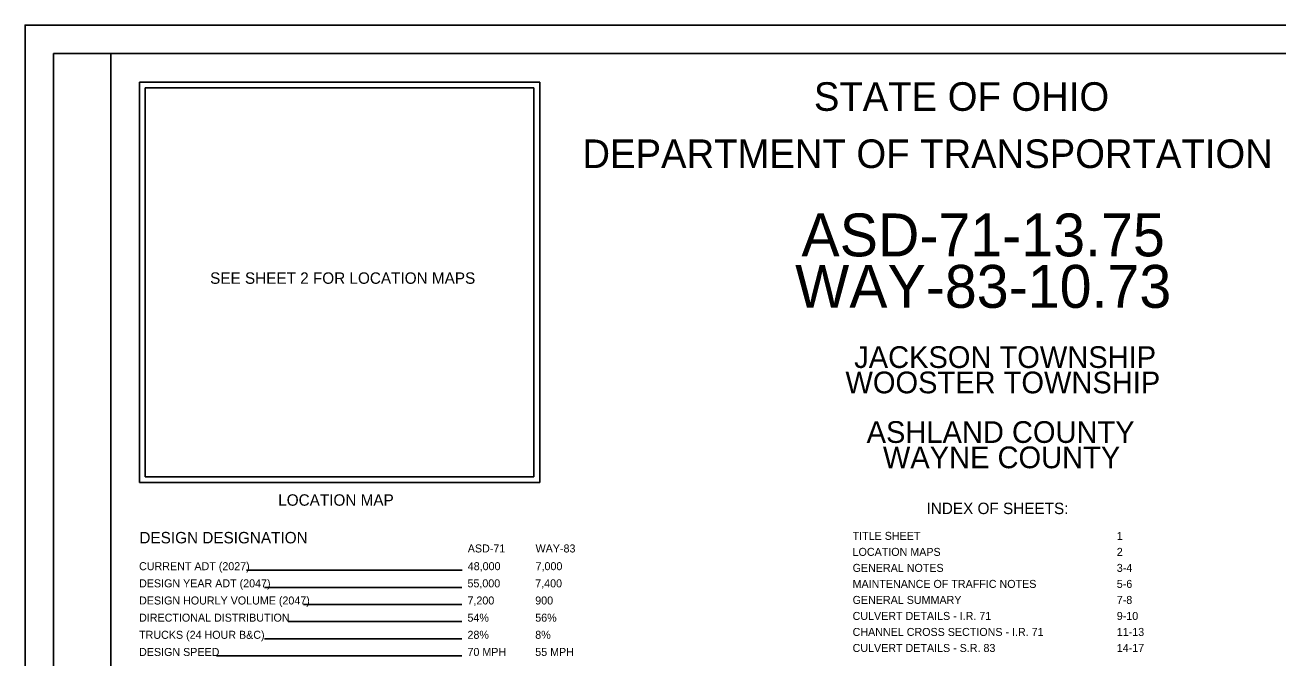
# Model space of a CAD drawing. Extents: x 0 to 34, y 0 to 22.
# Drawn here: x 0 to 21.91, y 10.93 to 22 of the extents above; entities that cross this region are included whole.
import ezdxf

# ---------------------------------------------------------------- set-up
doc = ezdxf.new("R2010")
doc.units = 0
for name, color, linetype in [('SH_Border', 7, 'Continuous'), ('SH_Cut_Line', 7, 'Continuous'), ('SH_Data', 7, 'Continuous'), ('SH_Text', 7, 'Continuous')]:
    doc.layers.add(name, color=color, linetype=linetype)

msp = doc.modelspace()

# ---------------------------------------------------------------- linework, layer by layer
at = {"layer": 'SH_Border'}
for points in [[(0.5, 21.5), (1.5, 21.5), (1.5, 0.5), (0.5, 0.5)], [(1.5, 21.5), (33.5, 21.5), (33.5, 0.5), (1.5, 0.5)]]:
    msp.add_lwpolyline(points, close=True, dxfattribs=at)
at = {"layer": 'SH_Cut_Line'}
msp.add_lwpolyline([(0, 0), (34, 0), (34, 22), (0, 22)], close=True, dxfattribs=at)
at = {"layer": 'SH_Data'}
for p, q in [((2, 21), (9, 21)), ((2, 21), (2, 14)), ((2.1, 20.9), (2.1, 14.1)), ((2.1, 20.9), (8.9, 20.9)), ((8.9, 20.9), (8.9, 14.1)), ((9, 21), (9, 14)), ((2.1, 14.1), (8.9, 14.1)), ((2.1, 14.1), (2.1, 14.1)), ((2, 14), (9, 14)), ((7.642, 12.467), (3.871, 12.467)), ((7.637, 12.167), (4.189, 12.167)), ((7.637, 11.867), (4.872, 11.867)), ((7.637, 11.567), (4.604, 11.567)), ((7.637, 11.267), (4.189, 11.267)), ((7.637, 10.967), (3.346, 10.967))]:
    msp.add_line(p, q, dxfattribs=at)

# ---------------------------------------------------------------- texts
msp.add_text('DESIGN DESIGNATION', height=0.2, dxfattribs=at).set_placement((2, 12.936))
at = {"layer": 'SH_Text'}
for s, height, p in [('STATE OF OHIO', 0.5, (13.795, 20.5)), ('DEPARTMENT OF TRANSPORTATION', 0.5, (9.747, 19.5)), ('ASD-71-13.75', 0.75, (13.577, 17.955)), ('WAY-83-10.73', 0.75, (13.467, 17.055)), ('SEE SHEET 2 FOR LOCATION MAPS', 0.2, (3.236, 17.475)), ('JACKSON TOWNSHIP', 0.38, (14.5, 16.003)), ('WOOSTER TOWNSHIP', 0.38, (14.347, 15.56)), ('ASHLAND COUNTY', 0.38, (14.717, 14.693)), ('WAYNE COUNTY', 0.38, (15.002, 14.25)), ('LOCATION MAP', 0.2, (4.427, 13.594)), ('INDEX OF SHEETS:', 0.2, (15.765, 13.448)), ('TITLE SHEET', 0.14, (14.472, 12.997)), ('1', 0.14, (19.092, 12.997)), ('ASD-71', 0.14, (7.742, 12.777)), ('WAY-83', 0.14, (8.928, 12.777)), ('LOCATION MAPS', 0.14, (14.472, 12.717)), ('2', 0.14, (19.092, 12.717)), ('CURRENT ADT (2027)', 0.14, (1.994, 12.467)), ('48,000', 0.14, (7.742, 12.467)), ('7,000', 0.14, (8.928, 12.467)), ('GENERAL NOTES', 0.14, (14.472, 12.437)), ('3-4', 0.14, (19.092, 12.437)), ('DESIGN YEAR ADT (2047)', 0.14, (1.994, 12.167)), ('55,000', 0.14, (7.737, 12.167)), ('7,400', 0.14, (8.922, 12.167)), ('MAINTENANCE OF TRAFFIC NOTES', 0.14, (14.472, 12.157)), ('5-6', 0.14, (19.092, 12.157)), ('DESIGN HOURLY VOLUME (2047)', 0.14, (1.994, 11.867)), ('7,200', 0.14, (7.737, 11.867)), ('900', 0.14, (8.922, 11.867)), ('GENERAL SUMMARY', 0.14, (14.472, 11.877)), ('7-8', 0.14, (19.092, 11.877)), ('DIRECTIONAL DISTRIBUTION', 0.14, (1.994, 11.567)), ('54%', 0.14, (7.737, 11.567)), ('56%', 0.14, (8.922, 11.567)), ('CULVERT DETAILS - I.R. 71', 0.14, (14.472, 11.597)), ('9-10', 0.14, (19.092, 11.597)), ('TRUCKS (24 HOUR B&C)', 0.14, (1.994, 11.267)), ('28%', 0.14, (7.737, 11.267)), ('8%', 0.14, (8.922, 11.267)), ('CHANNEL CROSS SECTIONS - I.R. 71', 0.14, (14.472, 11.317)), ('11-13', 0.14, (19.092, 11.317)), ('CULVERT DETAILS - S.R. 83', 0.14, (14.472, 11.037)), ('14-17', 0.14, (19.092, 11.037)), ('DESIGN SPEED', 0.14, (1.994, 10.967)), ('70 MPH', 0.14, (7.737, 10.967)), ('55 MPH', 0.14, (8.922, 10.967))]:
    msp.add_text(s, height=height, dxfattribs=at).set_placement(p)

doc.saveas('drawing.dxf')
